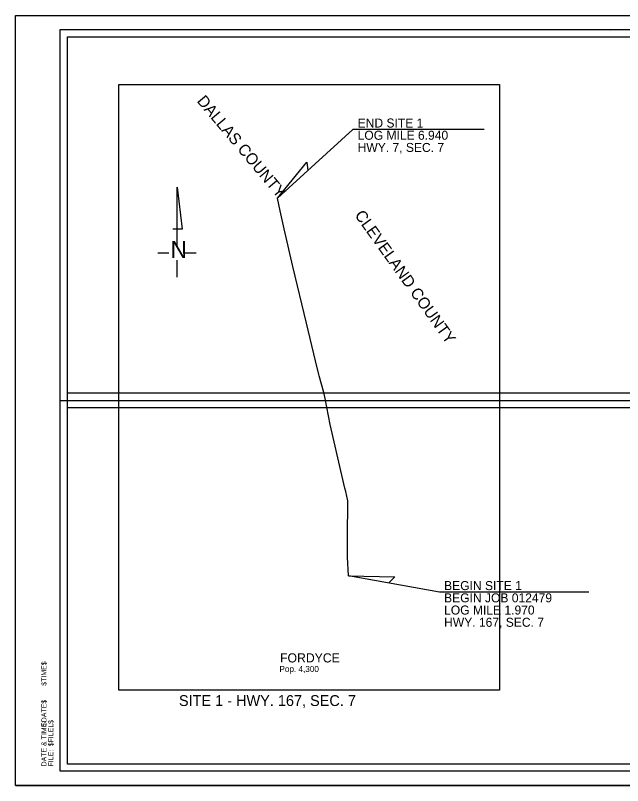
# Model space of a CAD drawing. Extents: x 10700 to 22009, y 10612 to 15552.
# Drawn here: x 10700 to 12382, y 13419 to 15552 of the extents above; entities that cross this region are included whole.
import ezdxf

# ---------------------------------------------------------------- set-up
doc = ezdxf.new("R2010")
doc.units = 0
for name, color, linetype in [('30', 7, 'Continuous'), ('6', 7, 'Continuous'), ('Default', 7, 'Continuous'), ('R_Border', 7, 'Continuous'), ('R_Border Plan-Plan', 7, 'Continuous'), ('R_Dimension', 7, 'Continuous'), ('R_Draft', 7, 'Continuous'), ('R_No Plot', 7, 'Continuous')]:
    doc.layers.add(name, color=color, linetype=linetype)

msp = doc.modelspace()

# ---------------------------------------------------------------- linework, layer by layer
at = {"layer": 'Default'}
msp.add_lwpolyline([(11622.6, 13999.8), (11620.3, 14051.4), (11619.8, 14105.4), (11620.5, 14207.8), (11615.4, 14232.9), (11613, 14242.8), (11590.3, 14338.7), (11585.4, 14359.3), (11572.4, 14418.6), (11557.9, 14491.1), (11554.5, 14507.7), (11541.6, 14554.1), (11540.6, 14557.3), (11531.2, 14595.3), (11506, 14699.4), (11469, 14856.8), (11444.2, 14960.6), (11433.4, 15010.5), (11426.3, 15045.4)], dxfattribs=at)
at = {"layer": 'R_Border'}
for p, q in [((10823.8, 15513.1), (13985.6, 15513.1)), ((10823.8, 13458.5), (10823.8, 15513.1)), ((12349, 15510.5), (12349, 15510.5)), ((12349, 15510.5), (12349, 15510.5)), ((10823.8, 13458.5), (10823.8, 13458.5)), ((13985.6, 13458.5), (10823.8, 13458.5))]:
    msp.add_line(p, q, dxfattribs=at)
at = {"layer": 'R_Border Plan-Plan'}
msp.add_line((10823.8, 14485.8), (13985.6, 14485.8), dxfattribs=at)
at = {"layer": 'R_Dimension'}
for p, q in [((11998.9, 15236.2), (11635.1, 15236.2)), ((12289.1, 13954.9), (11874.6, 13954.9))]:
    msp.add_line(p, q, dxfattribs=at)
for points in [[(11635.1, 15236.2), (11426.3, 15045.4), (11507.1, 15145.5), (11510.4, 15122.3)], [(11874.6, 13954.9), (11622.6, 13999.8), (11751.2, 13996.6), (11734.8, 13979.9)]]:
    msp.add_lwpolyline(points, dxfattribs=at)
at = {"layer": 'R_Draft'}
for p, q in [((11147.6, 15076.6), (11162.2, 14960.2)), ((11147.6, 14913.9), (11147.6, 15076.6)), ((11136.3, 14961.1), (11162.2, 14961.1)), ((11094.1, 14894.7), (11124.9, 14894.7)), ((11168.1, 14894.7), (11201.1, 14894.7)), ((11147.6, 14826.6), (11147.6, 14874.4))]:
    msp.add_line(p, q, dxfattribs=at)
at = {"layer": 'R_No Plot'}
for p, q in [((10699.8, 15552.1), (14033.1, 15552.1)), ((10699.8, 13418.7), (14033.1, 13418.7))]:
    msp.add_line(p, q, dxfattribs=at)
for points in [[(10699.7, 15552.1), (14033.1, 15552.1), (14033.1, 13418.7), (10699.7, 13418.7)], [(10843.8, 15493.1), (13339.2, 15493.1), (13339.2, 15394.3), (13514.6, 15394.3), (13755.6, 15394.3), (13755.6, 15171), (13965.6, 15171), (13965.6, 13478.5), (10843.8, 13478.5)], [(13965.6, 14505.8), (10843.8, 14505.8), (10843.8, 15493.1), (13339.2, 15493.1), (13339.2, 15394.3), (13514.6, 15394.3), (13755.6, 15394.3), (13755.6, 15171), (13965.6, 15171)], [(10986.5, 15360.8), (12041, 15360.8), (12041, 13682.8), (10986.5, 13682.8)], [(10843.8, 14465.8), (13965.6, 14465.8), (13965.6, 13478.5), (10843.8, 13478.5)]]:
    msp.add_lwpolyline(points, close=True, dxfattribs=at)

# ---------------------------------------------------------------- texts
at = {"layer": '30'}
for s, rotation, p in [('DALLAS COUNTY', 310, (11201.1, 15314.2)), ('CLEVELAND COUNTY', 305.6244, (11638.5, 14998.6))]:
    msp.add_text(s, height=31.68, rotation=rotation, dxfattribs=at).set_placement(p)
at = {"layer": '6'}
for s, height, p in [('FORDYCE', 25.34, (11433.1, 13759.8)), ('Pop. 4,300', 16.9, (11431.5, 13733.3))]:
    msp.add_text(s, height=height, dxfattribs=at).set_placement(p)
at = {"layer": 'Default'}
for s, height, p in [('$TIME$', 13.97, (10785.8, 13695.2)), ('$DATE$', 13.97, (10785.8, 13583.5)), ('DATE & TIME:', 13.968, (10785.8, 13471.8)), ('$FILEL$', 13.97, (10805, 13527.6)), ('FILE: ', 13.97, (10805, 13471.8))]:
    msp.add_text(s, height=height, rotation=90, dxfattribs=at).set_placement(p)
at = {"layer": 'R_Dimension'}
for s, height, rotation, p in [('END SITE 1', 25, 359.9994, (11648.1, 15241.5)), ('LOG MILE 6.940', 25, 359.9994, (11648.1, 15207.6)), ('HWY. 7, SEC. 7', 25, 359.9994, (11648.1, 15173.8)), ('BEGIN SITE 1', 25, 359.9999, (11887.7, 13960.2)), ('BEGIN JOB 012479', 25, 359.9999, (11887.7, 13926.3)), ('LOG MILE 1.970', 25, 359.9999, (11887.7, 13892.5)), ('HWY. 167, SEC. 7', 25, 359.9999, (11887.7, 13858.6)), ('SITE 1 - HWY. 167, SEC. 7', 30, 359.9999, (11152.9, 13639.2))]:
    msp.add_text(s, height=height, rotation=rotation, dxfattribs=at).set_placement(p)
at = {"layer": 'R_Draft'}
msp.add_text('N', height=46.5, dxfattribs=at).set_placement((11129.9, 14880.4))

doc.saveas('drawing.dxf')
